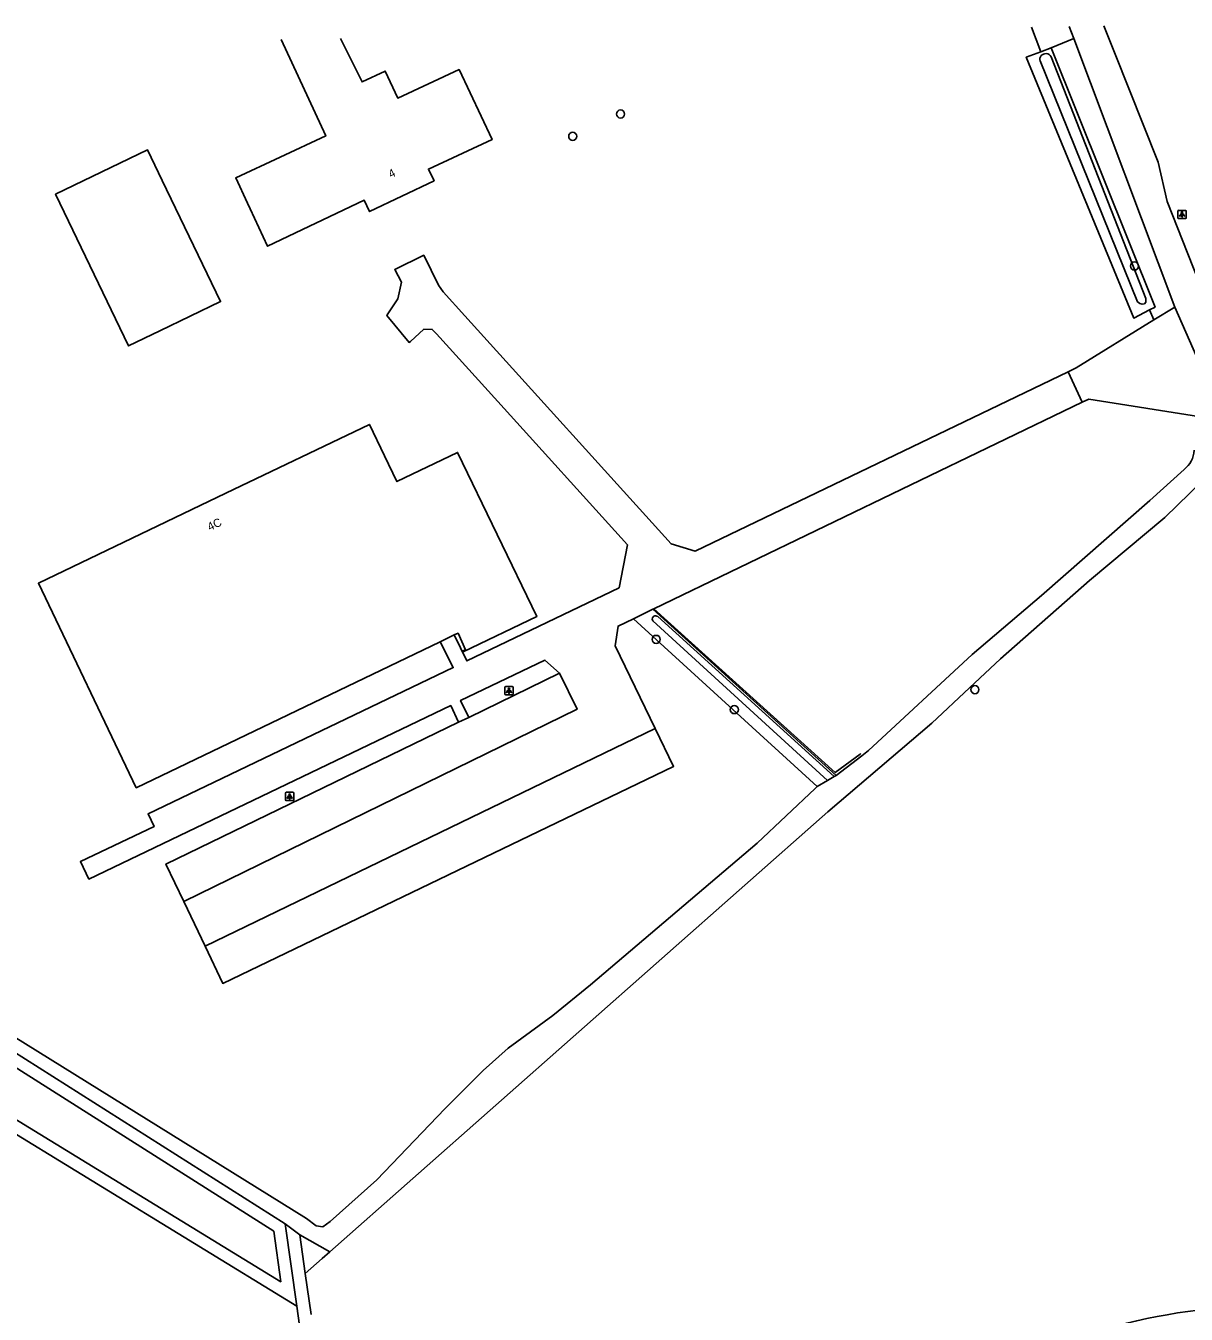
# Model space of a CAD drawing. Extents: x 161389 to 162585, y 388479 to 389761.
# Drawn here: x 162288.4 to 162428.4, y 389597.7 to 389753.2 of the extents above; entities that cross this region are included whole.
import ezdxf

# ---------------------------------------------------------------- set-up
doc = ezdxf.new("R2010")
doc.units = 0
for name, color, linetype in [('IMGEO_Berm_groen', 7, 'Continuous'), ('IMGEO_Boom', 7, 'Continuous'), ('IMGEO_Erf', 7, 'Continuous'), ('IMGEO_Gemengd_bos', 7, 'Continuous'), ('IMGEO_Groenvoorziening', 7, 'Continuous'), ('IMGEO_Hek', 7, 'Continuous'), ('IMGEO_Lichtpunt', 7, 'Continuous'), ('IMGEO_Loofbos', 7, 'Continuous'), ('IMGEO_Pand', 7, 'Continuous'), ('IMGEO_Pand_nummerreeks', 7, 'Continuous'), ('IMGEO_Parkeervlak_open', 7, 'Continuous'), ('IMGEO_Rijbaan_lokaal_gesloten', 7, 'Continuous'), ('IMGEO_Rijbaan_lokaal_open', 7, 'Continuous'), ('IMGEO_Waterloop', 7, 'Continuous')]:
    doc.layers.add(name, color=color, linetype=linetype)

msp = doc.modelspace()

# ---------------------------------------------------------------- linework, layer by layer
at = {"layer": 'IMGEO_Berm_groen'}
for points in [[(162412.08, 389750.54), (162414.82, 389751.67)], [(162412.08, 389750.54), (162424.63, 389719.27), (162423.97, 389718.93)], [(162424.48, 389717.71), (162423.97, 389718.93)]]:
    msp.add_lwpolyline(points, dxfattribs=at)
at = {"layer": 'IMGEO_Boom'}
for centre in [(162360.14, 389742.56), (162354.37, 389739.87), (162422.14, 389724.23), (162364.44, 389679.17), (162402.89, 389673.11), (162373.87, 389670.7)]:
    msp.add_circle(centre, 0.489, dxfattribs=at)
at = {"layer": 'IMGEO_Erf'}
for points in [[(162423.97, 389718.93), (162422.05, 389717.94), (162409.08, 389749.41), (162410.86, 389750.08)], [(162383.86, 389661.41), (162361.69, 389681.67)], [(162364.04, 389682.81), (162386.14, 389662.75)]]:
    msp.add_lwpolyline(points, dxfattribs=at)
at = {"layer": 'IMGEO_Gemengd_bos'}
msp.add_lwpolyline([(162321.07, 389598.73), (162271.67, 389628.98), (162262.97, 389614.25), (162261.33, 389609.47)], dxfattribs=at)
at = {"layer": 'IMGEO_Groenvoorziening'}
for points in [[(162410.86, 389750.08), (162409.7, 389753.06)], [(162410.86, 389750.08), (162412.08, 389750.54)]]:
    msp.add_lwpolyline(points, dxfattribs=at)
at = {"layer": 'IMGEO_Hek'}
for points in [[(162415.83, 389707.79), (162414.14, 389711.47)], [(162389.12, 389665.4), (162389.04, 389665.33), (162386.02, 389663.1), (162364.15, 389682.86)]]:
    msp.add_lwpolyline(points, dxfattribs=at)
at = {"layer": 'IMGEO_Lichtpunt'}
for p, q in [((162427.38, 389730.85), (162427.38, 389730.04)), ((162427.38, 389730.85), (162427.38, 389730.04)), ((162428.28, 389730.94), (162427.48, 389730.94)), ((162428.28, 389730.94), (162427.48, 389730.94)), ((162427.48, 389729.95), (162428.28, 389729.95)), ((162427.48, 389729.95), (162428.28, 389729.95)), ((162428.38, 389730.04), (162428.38, 389730.85)), ((162428.38, 389730.04), (162428.38, 389730.85)), ((162346.19, 389673.38), (162346.19, 389672.58)), ((162346.19, 389673.38), (162346.19, 389672.58)), ((162347.09, 389673.48), (162346.28, 389673.48)), ((162347.09, 389673.48), (162346.28, 389673.48)), ((162346.28, 389672.48), (162347.09, 389672.48)), ((162346.28, 389672.48), (162347.09, 389672.48)), ((162347.18, 389672.58), (162347.18, 389673.38)), ((162347.18, 389672.58), (162347.18, 389673.38)), ((162319.73, 389660.62), (162319.73, 389659.81)), ((162319.73, 389660.62), (162319.73, 389659.81)), ((162320.63, 389660.72), (162319.82, 389660.72)), ((162320.63, 389660.72), (162319.82, 389660.72)), ((162319.82, 389659.72), (162320.63, 389659.72)), ((162319.82, 389659.72), (162320.63, 389659.72)), ((162320.73, 389659.81), (162320.73, 389660.62)), ((162320.73, 389659.81), (162320.73, 389660.62))]:
    msp.add_line(p, q, dxfattribs=at)
for points in [[(162427.76, 389730.51), (162427.8, 389730.48), (162427.61, 389730.22), (162427.57, 389730.25), (162427.76, 389730.51)], [(162427.86, 389730.46), (162427.91, 389730.46), (162427.91, 389730.14), (162427.86, 389730.14), (162427.86, 389730.46)], [(162427.97, 389730.48), (162428.01, 389730.51), (162428.19, 389730.25), (162428.16, 389730.22), (162427.97, 389730.48)], [(162346.56, 389673.05), (162346.6, 389673.02), (162346.41, 389672.76), (162346.37, 389672.78), (162346.56, 389673.05)], [(162346.66, 389673), (162346.71, 389673), (162346.71, 389672.68), (162346.66, 389672.68), (162346.66, 389673)], [(162346.77, 389673.02), (162346.81, 389673.05), (162347, 389672.78), (162346.96, 389672.76), (162346.77, 389673.02)], [(162320.1, 389660.28), (162320.14, 389660.26), (162319.95, 389659.99), (162319.92, 389660.02), (162320.1, 389660.28)], [(162320.2, 389660.24), (162320.25, 389660.24), (162320.25, 389659.91), (162320.2, 389659.91), (162320.2, 389660.24)], [(162320.31, 389660.26), (162320.35, 389660.28), (162320.54, 389660.02), (162320.5, 389659.99), (162320.31, 389660.26)]]:
    msp.add_lwpolyline(points, dxfattribs=at)
for centre in [(162427.88, 389730.65), (162346.69, 389673.18), (162320.23, 389660.42)]:
    msp.add_circle(centre, 0.0994, dxfattribs=at)
for centre, start, end in [((162427.48, 389730.85), 90, 180), ((162427.48, 389730.85), 90, 180), ((162427.48, 389730.04), 180, 270), ((162427.48, 389730.04), 180, 270), ((162428.28, 389730.85), 0, 90), ((162428.28, 389730.85), 0, 90), ((162428.28, 389730.04), 270, 0), ((162428.28, 389730.04), 270, 360), ((162346.28, 389673.38), 90, 180), ((162346.28, 389673.38), 90, 180), ((162346.28, 389672.58), 180, 270), ((162346.28, 389672.58), 180, 270), ((162347.09, 389673.38), 0, 90), ((162347.09, 389673.38), 0, 90), ((162347.09, 389672.58), 270, 0), ((162347.09, 389672.58), 270, 360), ((162319.82, 389660.62), 90, 180), ((162319.82, 389660.62), 90, 180), ((162319.82, 389659.81), 180, 270), ((162319.82, 389659.81), 180, 270), ((162320.63, 389660.62), 0, 90), ((162320.63, 389660.62), 0, 90), ((162320.63, 389659.81), 270, 0), ((162320.63, 389659.81), 270, 360)]:
    msp.add_arc(centre, 0.0946, start, end, dxfattribs=at)
at = {"layer": 'IMGEO_Loofbos'}
for points in [[(162262.77, 389642.96), (162245.75, 389654.2), (162236.29, 389660.93), (162236.86, 389655.96), (162237.49, 389652.79), (162239.04, 389649.48), (162241.51, 389646.15), (162243.67, 389642.6), (162245.81, 389636.79), (162247.91, 389631.72), (162249.19, 389627.75), (162250.7, 389624.05), (162253.68, 389619.4), (162255.42, 389615.28), (162257.47, 389612.8), (162258.21, 389611.61), (162260.33, 389611.2), (162261.6, 389614.88), (162271.15, 389631.05), (162319.15, 389601.67), (162318.31, 389607.75), (162262.77, 389642.96)], [(162325.08, 389605.29), (162324.14, 389604.46), (162322.11, 389602.67)]]:
    msp.add_lwpolyline(points, dxfattribs=at)
at = {"layer": 'IMGEO_Pand'}
for points in [[(162315.44, 389731.14), (162315.13, 389731.8), (162313.71, 389734.86), (162319.06, 389737.35), (162324.58, 389739.91), (162319.18, 389751.54)], [(162326.35, 389751.66), (162328.96, 389746.44), (162331.76, 389747.74), (162333.27, 389744.49), (162340.67, 389747.93), (162344.64, 389739.48), (162336.96, 389735.91), (162337.64, 389734.5), (162329.87, 389730.79), (162329.2, 389732.17), (162317.54, 389726.6), (162315.44, 389731.14)], [(162304.58, 389716.41), (162300.79, 389714.59), (162291.99, 389732.89), (162303.08, 389738.22), (162304.85, 389734.54), (162311.88, 389719.92), (162304.58, 389716.41)], [(162338.36, 389678.88), (162301.72, 389661.27), (162289.91, 389685.95), (162312.54, 389696.81), (162329.85, 389705.11), (162331.68, 389701.31), (162333.17, 389698.21), (162340.48, 389701.73), (162350.04, 389681.93), (162341.16, 389677.66), (162341.11, 389677.8), (162341.43, 389677.93), (162340.54, 389679.92), (162340.08, 389679.71)], [(162340.08, 389679.71), (162338.36, 389678.88)]]:
    msp.add_lwpolyline(points, dxfattribs=at)
at = {"layer": 'IMGEO_Parkeervlak_open'}
for points in [[(162352.76, 389675.1), (162341.83, 389669.75)], [(162307.45, 389647.53), (162305.29, 389652.06), (162340.59, 389669.18)], [(162364.33, 389668.41), (162366.54, 389663.85), (162312.16, 389637.67), (162310.02, 389642.15)]]:
    msp.add_lwpolyline(points, dxfattribs=at)
at = {"layer": 'IMGEO_Rijbaan_lokaal_gesloten'}
for points in [[(162414.24, 389753.14), (162414.82, 389751.67)], [(162431.05, 389719.38), (162426.09, 389732), (162425, 389736.75), (162419.72, 389750), (162418.44, 389753.21)], [(162414.82, 389751.67), (162426.99, 389719.26)], [(162426.99, 389719.26), (162433.05, 389705.55)]]:
    msp.add_lwpolyline(points, dxfattribs=at)
at = {"layer": 'IMGEO_Rijbaan_lokaal_open'}
for points in [[(162340.08, 389679.71), (162341.58, 389676.58), (162359.97, 389685.41), (162360.96, 389690.57), (162345.32, 389707.88), (162337.92, 389716.02), (162337.42, 389716.58), (162336.42, 389716.6), (162334.78, 389715.13), (162334.63, 389715), (162331.93, 389718.24), (162332, 389718.35), (162333.28, 389720.28), (162333.73, 389722.28), (162332.91, 389723.81), (162336.4, 389725.53), (162338.18, 389721.9), (162338.74, 389721.1), (162341.35, 389718.21), (162366.23, 389690.69), (162369.14, 389689.82), (162414.14, 389711.47)], [(162424.48, 389717.71), (162426.99, 389719.26)], [(162414.14, 389711.47), (162415.11, 389711.94), (162424.48, 389717.71)], [(162414.14, 389711.47), (162415.83, 389707.79)], [(162415.83, 389707.79), (162364.15, 389682.86), (162364.04, 389682.81)], [(162430.63, 389705.94), (162416.62, 389708.17), (162415.83, 389707.79)], [(162361.69, 389681.67), (162359.84, 389680.78), (162359.5, 389678.39), (162364.33, 389668.41)], [(162364.04, 389682.81), (162361.69, 389681.67)], [(162340.59, 389669.18), (162339.65, 389671.19), (162296.01, 389650.25), (162294.98, 389652.36), (162303.87, 389656.59), (162303.14, 389658.13), (162339.96, 389675.77), (162338.36, 389678.88)], [(162341.83, 389669.75), (162340.84, 389671.8), (162351.01, 389676.68), (162352.76, 389675.1)], [(162307.45, 389647.53), (162354.89, 389670.75), (162352.76, 389675.1)], [(162341.83, 389669.75), (162340.59, 389669.18)], [(162364.33, 389668.41), (162310.02, 389642.15)], [(162310.02, 389642.15), (162307.45, 389647.53)]]:
    msp.add_lwpolyline(points, dxfattribs=at)
at = {"layer": 'IMGEO_Waterloop'}
for points in [[(162412.08, 389749.46), (162423.52, 389720.29), (162423.51, 389719.85), (162423.33, 389719.66), (162423.05, 389719.61), (162422.78, 389719.71), (162422.52, 389719.9), (162410.76, 389748.96)], [(162325.08, 389605.29), (162385.15, 389658.37), (162397.7, 389669.06), (162402.25, 389673.34), (162405.96, 389676.81), (162416.7, 389686.29), (162425.82, 389693.87), (162430.29, 389698.26), (162431.13, 389699.42)], [(162386.14, 389662.75), (162389.24, 389665.14), (162390.05, 389665.76), (162402.57, 389677.34), (162410.94, 389684.45), (162424.01, 389695.91), (162428.12, 389699.68)], [(162385.11, 389662.15), (162364.02, 389681.42), (162363.97, 389681.61)], [(162364.47, 389681.99), (162364.63, 389681.93), (162385.9, 389662.62)], [(162236.3, 389662.76), (162246.6, 389655.44), (162263.58, 389644.22), (162319.7, 389608.65)], [(162236.79, 389663.92), (162262.65, 389646.64), (162283.86, 389633.15), (162322.24, 389609.3), (162323.41, 389608.41), (162324.23, 389608.31), (162325.1, 389608.92), (162330.73, 389613.98), (162338.96, 389622.53), (162343.56, 389627.15), (162346.58, 389629.85), (162351.96, 389633.79), (162356.51, 389637.5), (162376.62, 389654.57), (162383.61, 389661.17), (162383.86, 389661.41)], [(162386.14, 389662.75), (162385.9, 389662.62)], [(162385.11, 389662.15), (162383.86, 389661.41)], [(162385.9, 389662.62), (162385.11, 389662.15)], [(162319.7, 389608.65), (162321.46, 389607.34)], [(162319.7, 389608.65), (162321.07, 389598.73)], [(162321.46, 389607.34), (162325.08, 389605.29)], [(162321.46, 389607.34), (162322.11, 389602.67)], [(162322.11, 389602.67), (162322.8, 389597.7)], [(162328.57, 389545.88), (162328, 389548.66), (162321.07, 389598.73)]]:
    msp.add_lwpolyline(points, dxfattribs=at)
for centre, radius, start, end in [((162411.56, 389748.81), 1.05, 94.561, 129.7157), ((162411.51, 389749.24), 0.607, 20.7507, 93.3286), ((162411.39, 389749.17), 0.664, 138.6021, 198.6767), ((162426.35, 389702.07), 2.98, 306.463, 358.5648), ((162364.38, 389681.64), 0.407, 139.4323, 183.4601), ((162364.35, 389681.59), 0.422, 73.9719, 131.7859), ((162439.59, 389520.52), 78.34, 88.8894, 118.2652)]:
    msp.add_arc(centre, radius, start, end, dxfattribs=at)

# ---------------------------------------------------------------- texts
at = {"layer": 'IMGEO_Pand_nummerreeks'}
for s, rotation, p in [('4', 25.5477, (162332.42, 389734.8)), ('4C', 25.6384, (162310.59, 389692.23))]:
    msp.add_text(s, height=1, rotation=rotation, dxfattribs=at).set_placement(p)

doc.saveas('drawing.dxf')
